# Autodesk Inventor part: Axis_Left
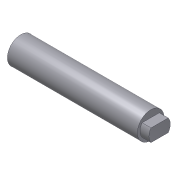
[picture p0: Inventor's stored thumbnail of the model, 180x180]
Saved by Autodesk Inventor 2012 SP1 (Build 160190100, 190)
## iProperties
Created: 2006-03
Part Number: Axis_Left
Document SubType Name: Modeling
Material: Stainless Steel, 440C
Mass: 103.094 g
Surface Area: 39.6652 cm^2
Volume: 13.3025 cm^3
Density: 7.75 g/cm^3
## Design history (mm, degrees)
sketch "Sketch1"
  geometry: L1 (-4.823, 3.575)-(4.823, 3.575); L2 (4.823, 3.575)-(4.823, -3.575); L3 (4.823, -3.575)-(-4.822, -3.575); L4 (-4.822, -3.575)-(-4.823, 3.575); L5 (-4.823, 3.575)-(4.823, -3.575); L6 (-7.205, 0)-(9.606, 0) reference; A1 r 6 centre (-0.004, 0) between (-4.823, 3.575) and (-4.822, -3.575); A2 r 6 centre (0.004, 0) between (4.823, -3.575) and (4.823, 3.575); 2 further points
  constraints: 10 end point, 4 point on circle, 2 centre point, 2 parallel, 2 point on line, 1 coincident, 1 equal radius, 1 horizontal, 1 midpoint, 1 perpendicular
  dimensions: "d0" = 9.645 distance of L2.end L3.end; "d1" = 7.15 distance of L3.end L1.start; "d2" = 6 radius of A1
extrude "Extrusion1" new body sketch "Sketch1" distance "d3" = 5; taper "d4" = 0 deg
sketch "Sketch2"
  geometry: C1 r 7.5 at (0, 0); 1 further point
  constraints: 1 centre point, 1 coincident
  dimensions: "d5" = 15 diameter of C1
extrude "Extrusion2" join sketch "Sketch2" distance "d6" = 73; taper "d7" = 0 deg
body "Solid1"
